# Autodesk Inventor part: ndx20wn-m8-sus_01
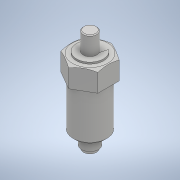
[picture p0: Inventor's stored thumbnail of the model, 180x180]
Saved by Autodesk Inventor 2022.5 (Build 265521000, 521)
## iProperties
Part Number: ndx20wn-m8-sus_01
Material: 一般
Document SubType Name: Modeling
Designer: ImaoCorp
Density: 1 g/cm^3
Appearance: 既定
Author: ImaoCorp
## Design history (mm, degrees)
feature "ndx20wn-m8-sus_01"
node "ソリッド1"
